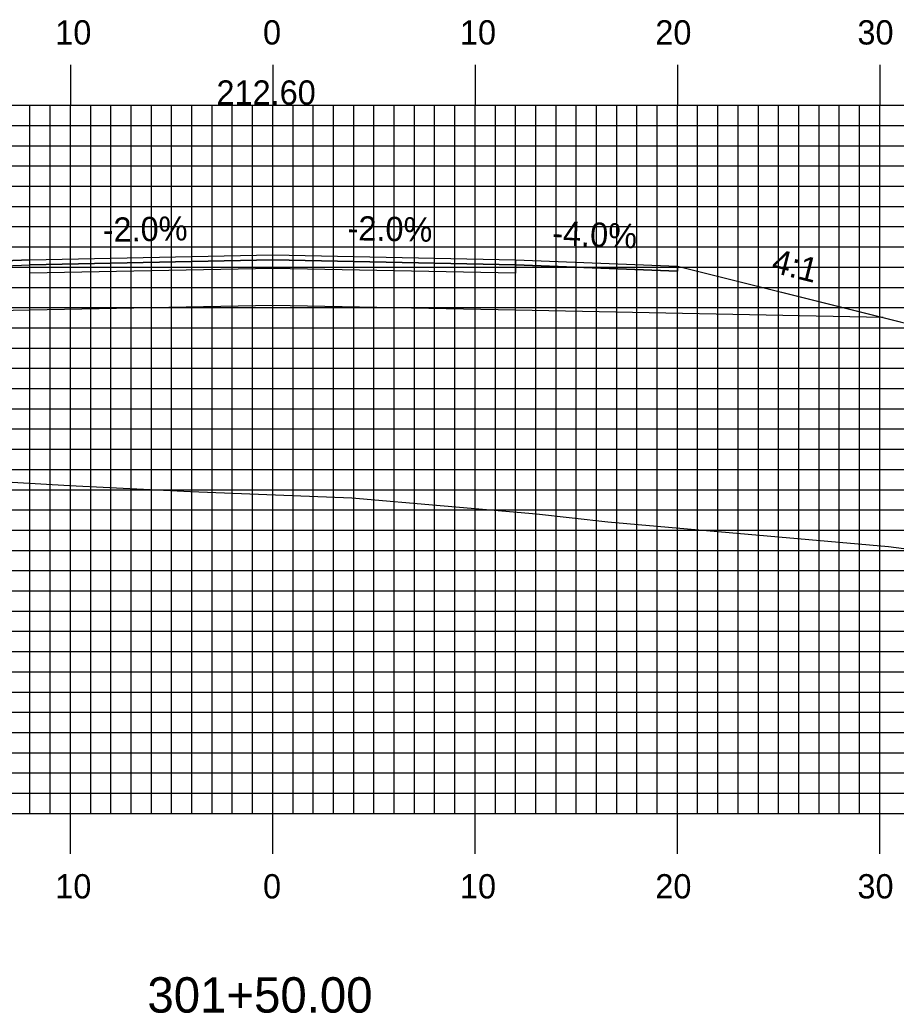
# Model space of a CAD drawing. Extents: x 1815702 to 1816046, y 442591 to 442811.
# Drawn here: x 1815855.55 to 1815898.86, y 442703.8 to 442752.88 of the extents above; entities that cross this region are included whole.
import ezdxf

# ---------------------------------------------------------------- set-up
doc = ezdxf.new("R2010")
doc.units = 0
for name, color, linetype in [('ANNOTATION', 7, 'Continuous'), ('D_Roadway_Centerline', 7, 'Continuous'), ('D_Roadway_Centerline_Text', 7, 'Continuous'), ('D_Roadway_Edge_Shoulder', 7, 'Continuous'), ('D_Roadway_Edge_TW', 7, 'Continuous'), ('D_Roadway_Pavement', 7, 'Continuous'), ('D_Roadway_SlopeLines', 7, 'Continuous'), ('D_Roadway_SubGrade', 7, 'Continuous'), ('H_V ANNOTATION', 7, 'Continuous'), ('MAJOR', 7, 'Continuous'), ('MINOR', 7, 'Continuous'), ('S_Roadway_Centerline', 7, 'Continuous')]:
    doc.layers.add(name, color=color, linetype=linetype)

msp = doc.modelspace()

# ---------------------------------------------------------------- linework, layer by layer
at = {"layer": 'D_Roadway_Centerline'}
msp.add_lwpolyline([(1815820.648, 442733.859), (1815836.047, 442737.709), (1815837.873, 442738.166), (1815848.047, 442740.709), (1815856.047, 442741.029), (1815868.047, 442741.269), (1815880.047, 442741.029), (1815888.047, 442740.709), (1815898.221, 442738.166), (1815900.047, 442737.709), (1815942.232, 442723.647)], dxfattribs=at)
at = {"layer": 'D_Roadway_Edge_Shoulder'}
for points in [[(1815856.047, 442741.029), (1815848.047, 442740.709), (1815848.047, 442740.459), (1815856.047, 442740.779)], [(1815880.047, 442741.029), (1815888.047, 442740.709), (1815888.047, 442740.459), (1815880.047, 442740.779)]]:
    msp.add_lwpolyline(points, close=True, dxfattribs=at)
at = {"layer": 'D_Roadway_Edge_TW'}
msp.add_lwpolyline([(1815856.047, 442740.779), (1815856.047, 442741.029), (1815868.047, 442741.269), (1815880.047, 442741.029), (1815880.047, 442740.779), (1815868.047, 442741.019)], close=True, dxfattribs=at)
at = {"layer": 'D_Roadway_Pavement'}
msp.add_lwpolyline([(1815856.047, 442740.362), (1815856.047, 442740.779), (1815868.047, 442741.019), (1815880.047, 442740.779), (1815880.047, 442740.362), (1815868.047, 442740.602)], close=True, dxfattribs=at)
at = {"layer": 'D_Roadway_SlopeLines'}
msp.add_lwpolyline([(1815888.047, 442740.709), (1815900.047, 442737.709), (1815942.232, 442723.647)], dxfattribs=at)
at = {"layer": 'D_Roadway_SubGrade'}
msp.add_lwpolyline([(1815856.047, 442738.529), (1815837.873, 442738.166), (1815848.047, 442740.709), (1815848.047, 442740.459), (1815856.047, 442740.779), (1815868.047, 442741.019), (1815880.047, 442740.779), (1815888.047, 442740.459), (1815888.047, 442740.709), (1815898.221, 442738.166), (1815880.047, 442738.529), (1815868.047, 442738.769)], close=True, dxfattribs=at)
at = {"layer": 'MAJOR'}
for p, q in [((1815858.047, 442750.669), (1815858.047, 442748.665)), ((1815868.047, 442750.669), (1815868.047, 442748.665)), ((1815878.047, 442750.669), (1815878.047, 442748.665)), ((1815888.047, 442750.669), (1815888.047, 442748.665)), ((1815898.047, 442750.669), (1815898.047, 442748.665)), ((1815728.047, 442748.665), (1816008.047, 442748.665)), ((1815728.047, 442748.665), (1816008.047, 442748.665)), ((1815858.047, 442713.665), (1815858.047, 442748.665)), ((1815868.047, 442713.665), (1815868.047, 442748.665)), ((1815878.047, 442713.665), (1815878.047, 442748.665)), ((1815888.047, 442713.665), (1815888.047, 442748.665)), ((1815898.047, 442713.665), (1815898.047, 442748.665)), ((1815728.047, 442743.665), (1816008.047, 442743.665)), ((1815728.047, 442738.665), (1816008.047, 442738.665)), ((1815728.047, 442733.665), (1816008.047, 442733.665)), ((1815728.047, 442728.665), (1816008.047, 442728.665)), ((1815728.047, 442723.665), (1816008.047, 442723.665)), ((1815728.047, 442718.665), (1816008.047, 442718.665)), ((1815728.047, 442713.665), (1816008.047, 442713.665)), ((1815728.047, 442713.665), (1816008.047, 442713.665)), ((1815858.047, 442711.661), (1815858.047, 442713.665)), ((1815868.047, 442711.661), (1815868.047, 442713.665)), ((1815878.047, 442711.661), (1815878.047, 442713.665)), ((1815888.047, 442711.661), (1815888.047, 442713.665)), ((1815898.047, 442711.661), (1815898.047, 442713.665))]:
    msp.add_line(p, q, dxfattribs=at)
at = {"layer": 'MINOR'}
for p, q in [((1815856.047, 442713.665), (1815856.047, 442748.665)), ((1815857.047, 442713.665), (1815857.047, 442748.665)), ((1815859.047, 442713.665), (1815859.047, 442748.665)), ((1815860.047, 442713.665), (1815860.047, 442748.665)), ((1815861.047, 442713.665), (1815861.047, 442748.665)), ((1815862.047, 442713.665), (1815862.047, 442748.665)), ((1815863.047, 442713.665), (1815863.047, 442748.665)), ((1815864.047, 442713.665), (1815864.047, 442748.665)), ((1815865.047, 442713.665), (1815865.047, 442748.665)), ((1815866.047, 442713.665), (1815866.047, 442748.665)), ((1815867.047, 442713.665), (1815867.047, 442748.665)), ((1815869.047, 442713.665), (1815869.047, 442748.665)), ((1815870.047, 442713.665), (1815870.047, 442748.665)), ((1815871.047, 442713.665), (1815871.047, 442748.665)), ((1815872.047, 442713.665), (1815872.047, 442748.665)), ((1815873.047, 442713.665), (1815873.047, 442748.665)), ((1815874.047, 442713.665), (1815874.047, 442748.665)), ((1815875.047, 442713.665), (1815875.047, 442748.665)), ((1815876.047, 442713.665), (1815876.047, 442748.665)), ((1815877.047, 442713.665), (1815877.047, 442748.665)), ((1815879.047, 442713.665), (1815879.047, 442748.665)), ((1815880.047, 442713.665), (1815880.047, 442748.665)), ((1815881.047, 442713.665), (1815881.047, 442748.665)), ((1815882.047, 442713.665), (1815882.047, 442748.665)), ((1815883.047, 442713.665), (1815883.047, 442748.665)), ((1815884.047, 442713.665), (1815884.047, 442748.665)), ((1815885.047, 442713.665), (1815885.047, 442748.665)), ((1815886.047, 442713.665), (1815886.047, 442748.665)), ((1815887.047, 442713.665), (1815887.047, 442748.665)), ((1815889.047, 442713.665), (1815889.047, 442748.665)), ((1815890.047, 442713.665), (1815890.047, 442748.665)), ((1815891.047, 442713.665), (1815891.047, 442748.665)), ((1815892.047, 442713.665), (1815892.047, 442748.665)), ((1815893.047, 442713.665), (1815893.047, 442748.665)), ((1815894.047, 442713.665), (1815894.047, 442748.665)), ((1815895.047, 442713.665), (1815895.047, 442748.665)), ((1815896.047, 442713.665), (1815896.047, 442748.665)), ((1815897.047, 442713.665), (1815897.047, 442748.665)), ((1815728.047, 442747.665), (1816008.047, 442747.665)), ((1815728.047, 442746.665), (1816008.047, 442746.665)), ((1815728.047, 442745.665), (1816008.047, 442745.665)), ((1815728.047, 442744.665), (1816008.047, 442744.665)), ((1815728.047, 442742.665), (1816008.047, 442742.665)), ((1815728.047, 442741.665), (1816008.047, 442741.665)), ((1815728.047, 442740.665), (1816008.047, 442740.665)), ((1815728.047, 442739.665), (1816008.047, 442739.665)), ((1815728.047, 442737.665), (1816008.047, 442737.665)), ((1815728.047, 442736.665), (1816008.047, 442736.665)), ((1815728.047, 442735.665), (1816008.047, 442735.665)), ((1815728.047, 442734.665), (1816008.047, 442734.665)), ((1815728.047, 442732.665), (1816008.047, 442732.665)), ((1815728.047, 442731.665), (1816008.047, 442731.665)), ((1815728.047, 442730.665), (1816008.047, 442730.665)), ((1815728.047, 442729.665), (1816008.047, 442729.665)), ((1815728.047, 442727.665), (1816008.047, 442727.665)), ((1815728.047, 442726.665), (1816008.047, 442726.665)), ((1815728.047, 442725.665), (1816008.047, 442725.665)), ((1815728.047, 442724.665), (1816008.047, 442724.665)), ((1815728.047, 442722.665), (1816008.047, 442722.665)), ((1815728.047, 442721.665), (1816008.047, 442721.665)), ((1815728.047, 442720.665), (1816008.047, 442720.665)), ((1815728.047, 442719.665), (1816008.047, 442719.665)), ((1815728.047, 442717.665), (1816008.047, 442717.665)), ((1815728.047, 442716.665), (1816008.047, 442716.665)), ((1815728.047, 442715.665), (1816008.047, 442715.665)), ((1815728.047, 442714.665), (1816008.047, 442714.665))]:
    msp.add_line(p, q, dxfattribs=at)
at = {"layer": 'S_Roadway_Centerline'}
msp.add_lwpolyline([(1815813.519, 442734.442), (1815817.669, 442734.085), (1815831.045, 442733.072), (1815831.857, 442733.018), (1815834.906, 442732.5), (1815845.169, 442730.68), (1815847.186, 442730.502), (1815858.008, 442729.871), (1815863.977, 442729.579), (1815871.952, 442729.261), (1815881.085, 442728.476), (1815884.611, 442728.07), (1815898.479, 442726.849), (1815912.254, 442725.064), (1815915.396, 442724.993), (1815920.236, 442724.754), (1815932.352, 442724.248), (1815944.057, 442723.536), (1815950.072, 442723.217)], dxfattribs=at)

# ---------------------------------------------------------------- texts
at = {"layer": 'ANNOTATION'}
for s, rotation, p in [('-2.0%', 1.1458, (1815859.653, 442741.902)), ('-2.0%', 358.8542, (1815871.733, 442741.996)), ('-4.0%', 357.7094, (1815881.839, 442741.759)), ('4:1', 345.9638, (1815892.64, 442740.422))]:
    msp.add_text(s, height=1.2, rotation=rotation, dxfattribs=at).set_placement(p)
at = {"layer": 'D_Roadway_Centerline'}
for s, p in [('C', (1815868.042, 442741.269)), ('L', (1815868.047, 442741.262))]:
    msp.add_text(s, height=0.0146, dxfattribs=at).set_placement(p)
at = {"layer": 'D_Roadway_Centerline_Text'}
msp.add_text('212.60', height=1.2, dxfattribs=at).set_placement((1815865.264, 442748.693))
at = {"layer": 'H_V ANNOTATION'}
for s, height, p in [('10', 1.2, (1815857.297, 442751.665)), ('0', 1.2, (1815867.565, 442751.665)), ('10', 1.2, (1815877.297, 442751.665)), ('20', 1.2, (1815886.955, 442751.665)), ('30', 1.2, (1815896.944, 442751.665)), ('10', 1.2, (1815857.297, 442709.465)), ('0', 1.2, (1815867.565, 442709.465)), ('10', 1.2, (1815877.297, 442709.465)), ('20', 1.2, (1815886.955, 442709.465)), ('30', 1.2, (1815896.944, 442709.465)), ('301+50.00', 1.75, (1815861.851, 442703.821))]:
    msp.add_text(s, height=height, dxfattribs=at).set_placement(p)

doc.saveas('drawing.dxf')
